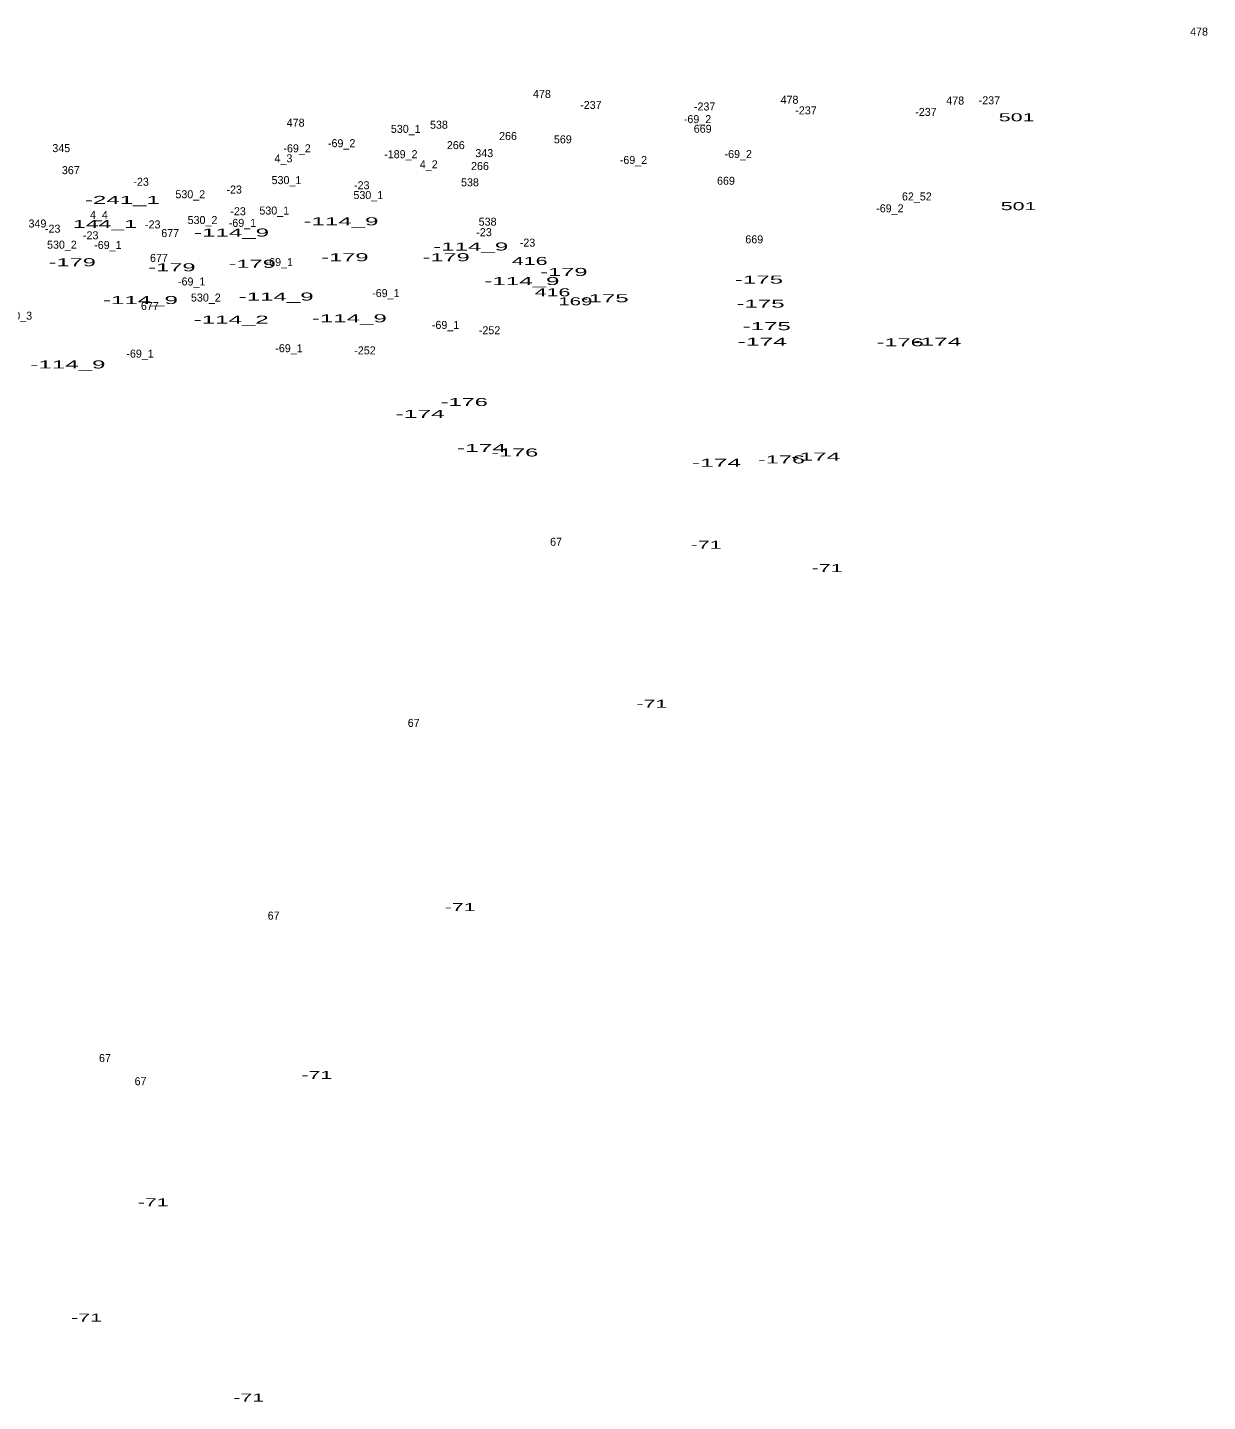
# Model space of a CAD drawing. Extents: x -661742 to -657295, y -1002932 to -996888.
# Drawn here: x -658122 to -657532, y -999067 to -998380 of the extents above; entities that cross this region are included whole.
import ezdxf
from ezdxf.enums import TextEntityAlignment as Align

# ---------------------------------------------------------------- set-up
doc = ezdxf.new("R2010")
doc.units = 0
doc.header["$LTSCALE"] = 1.6
doc.layers.add('24', color=7, linetype='Continuous')

msp = doc.modelspace()

# ---------------------------------------------------------------- texts
at = {"layer": '24'}
for s, p in [('478', (-657536.597, -998383.8)), ('478', (-657865.087, -998414.97)), ('-237', (-657840.611, -998420.47)), ('478', (-657741.327, -998417.88)), ('478', (-657658.497, -998418.27)), ('-237', (-657641.401, -998418.15)), ('-69_2', (-657787.313, -998427.56)), ('-237', (-657783.751, -998421.24)), ('-237', (-657733.081, -998423.18)), ('-237', (-657673.121, -998423.95)), ('478', (-657988.197, -998429.32)), ('530_1', (-657933.163, -998432.44)), ('538', (-657916.567, -998430.36)), ('669', (-657784.723, -998432.38)), ('-69_2', (-657965.203, -998439.59)), ('266', (-657908.128, -998440.56)), ('266', (-657882.028, -998436.02)), ('569', (-657854.628, -998437.66)), ('345', (-658105.351, -998442.05)), ('4_3', (-657994.281, -998447.17)), ('-69_2', (-657987.483, -998442.16)), ('-189_2', (-657935.592, -998445.08)), ('343', (-657893.911, -998444.55)), ('-69_2', (-657819.333, -998447.97)), ('-69_2', (-657766.953, -998445.01)), ('367', (-658100.588, -998453.07)), ('4_2', (-657921.671, -998450.17)), ('266', (-657896.048, -998451.01)), ('-23', (-658065.445, -998458.87)), ('530_1', (-657992.783, -998458.04)), ('-23', (-657955.135, -998460.61)), ('538', (-657901.057, -998459.15)), ('669', (-657773.093, -998458.37)), ('530_2', (-658040.859, -998465.11)), ('-23', (-658018.915, -998462.75)), ('530_1', (-657951.873, -998465.51)), ('62_52', (-657677.68, -998466.21)), ('4_4', (-658086.535, -998475.42)), ('-23', (-658016.975, -998473.61)), ('530_1', (-657998.883, -998473.26)), ('-69_2', (-657691.153, -998472.16)), ('349', (-658117.257, -998479.74)), ('-23', (-658109.645, -998482.33)), ('-23', (-658059.625, -998480.2)), ('530_2', (-658034.749, -998478.01)), ('-69_1', (-658014.787, -998479.43)), ('538', (-657892.237, -998478.84)), ('-23', (-658090.645, -998485.63)), ('677', (-658050.903, -998484.52)), ('-23', (-657894.005, -998484.08)), ('-23', (-657872.295, -998489.32)), ('669', (-657758.943, -998487.65)), ('530_2', (-658105.029, -998490.32)), ('-69_1', (-658082.057, -998490.48)), ('677', (-658056.523, -998496.93)), ('-69_1', (-657996.367, -998499.02)), ('-69_1', (-658040.177, -998508.71)), ('530_2', (-658033.069, -998516.75)), ('-69_1', (-657943.107, -998514.53)), ('677', (-658061.083, -998520.98)), ('530_3', (-658127.359, -998525.83)), ('-69_1', (-657913.257, -998530.44)), ('-252', (-657891.265, -998533.12)), ('-69_1', (-657991.517, -998542.07)), ('-252', (-657953.535, -998543.18)), ('-69_1', (-658065.967, -998544.79)), ('67', (-657858.018, -998638.85)), ('67', (-657929.188, -998729.39)), ('67', (-657999.198, -998825.74)), ('67', (-658083.518, -998896.94)), ('67', (-658065.728, -998908.54))]:
    msp.add_text(s, height=4, dxfattribs=at).set_placement(p, align=Align.CENTER)
for s, width, p in [('501', 2, (-657627.784, -998426.64)), ('-241_1', 2.25, (-658074.803, -998467.95)), ('501', 2, (-657626.814, -998471.06)), ('144_1', 2.15, (-658083.507, -998480)), ('-114_9', 2.25, (-657965.558, -998478.64)), ('-114_9', 2.25, (-658020.228, -998484.26)), ('-179', 2.2, (-657963.569, -998496.58)), ('-179', 2.2, (-657912.969, -998496.58)), ('-114_9', 2.25, (-657900.688, -998491.24)), ('-179', 2.2, (-658099.859, -998499.1)), ('-179', 2.2, (-658050.039, -998501.62)), ('-179', 2.2, (-658009.909, -998499.88)), ('416', 2, (-657871.188, -998498.45)), ('-114_9', 2.25, (-657875.098, -998508.5)), ('-179', 2.2, (-657854.109, -998503.95)), ('-175', 2.25, (-657756.585, -998507.79)), ('-114_9', 2.25, (-657997.938, -998516.26)), ('416', 2, (-657859.778, -998514.12)), ('-175', 2.25, (-657833.745, -998517.1)), ('-114_9', 2.25, (-658065.788, -998518)), ('169', 1.9, (-657848.367, -998518.61)), ('-175', 2.25, (-657755.805, -998519.81)), ('-114_2', 2.25, (-658020.413, -998527.79)), ('-114_9', 2.25, (-657961.368, -998527.12)), ('-175', 2.25, (-657752.705, -998531.06)), ('-174', 2.3, (-657754.941, -998538.82)), ('-176', 2.2, (-657685.989, -998539.11)), ('-174', 2.3, (-657667.701, -998538.82)), ('-114_9', 2.25, (-658102.038, -998550.2)), ('-176', 2.2, (-657903.899, -998568.98)), ('-174', 2.3, (-657925.931, -998574.89)), ('-174', 2.3, (-657895.301, -998591.96)), ('-176', 2.2, (-657878.699, -998594.19)), ('-174', 2.3, (-657777.811, -998599.33)), ('-176', 2.2, (-657745.319, -998597.68)), ('-174', 2.3, (-657728.181, -998596.22)), ('-71', 2, (-657783.015, -998640.34)), ('-71', 2, (-657722.535, -998651.98)), ('-71', 2, (-657810.155, -998719.85)), ('-71', 2, (-657905.935, -998821.48)), ('-71', 2, (-657977.585, -998905.41)), ('-71', 2, (-658059.395, -998969.03)), ('-71', 2, (-658092.705, -999026.71)), ('-71', 2, (-658011.665, -999066.66))]:
    msp.add_text(s, height=4, dxfattribs=dict(at, width=width)).set_placement(p, align=Align.CENTER)

doc.saveas('drawing.dxf')
